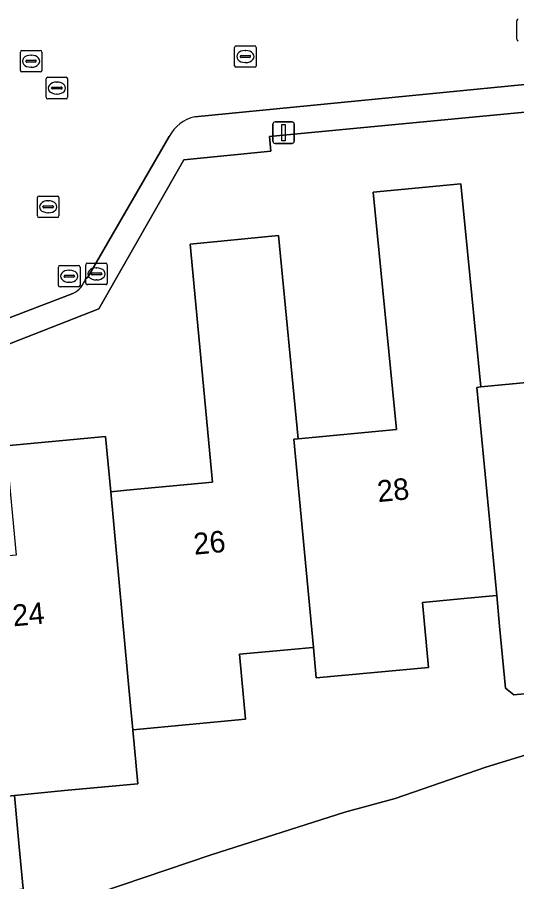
# Model space of a CAD drawing. Extents: x 157793 to 159380, y 380877 to 382313.
# Drawn here: x 158433.42 to 158456.61, y 381160.97 to 381201.1 of the extents above; entities that cross this region are included whole.
import ezdxf

# ---------------------------------------------------------------- set-up
doc = ezdxf.new("R2010")
doc.units = 0
for name, color, linetype in [('IMGEO_Brandkraan', 7, 'Continuous'), ('IMGEO_Erf', 7, 'Continuous'), ('IMGEO_Kolk', 7, 'Continuous'), ('IMGEO_Lichtmast', 7, 'Continuous'), ('IMGEO_Oever', 7, 'Continuous'), ('IMGEO_Pand', 7, 'Continuous'), ('IMGEO_Pand_nummerreeks', 7, 'Continuous'), ('IMGEO_Rijbaan_lokaal_open', 7, 'Continuous'), ('IMGEO_Rioolput', 7, 'Continuous'), ('IMGEO_Voetpad_open', 7, 'Continuous')]:
    doc.layers.add(name, color=color, linetype=linetype)

msp = doc.modelspace()

# ---------------------------------------------------------------- linework, layer by layer
at = {"layer": 'IMGEO_Brandkraan'}
for p, q in [((158436.596, 381188.76), (158436.596, 381189.612)), ((158436.671, 381189.686), (158437.523, 381189.686)), ((158437.084, 381189.466), (158437.109, 381189.466)), ((158437.597, 381189.612), (158437.597, 381188.76)), ((158436.855, 381189.18), (158436.855, 381189.192)), ((158437.293, 381189.143), (158436.895, 381189.143)), ((158436.898, 381189.229), (158437.296, 381189.229)), ((158437.339, 381189.192), (158437.339, 381189.18)), ((158437.523, 381188.686), (158436.671, 381188.686)), ((158437.107, 381188.906), (158437.082, 381188.906))]:
    msp.add_line(p, q, dxfattribs=at)
for points in [[(158436.596, 381188.76), (158436.596, 381189.612)], [(158436.671, 381189.686), (158437.523, 381189.686)], [(158437.597, 381189.612), (158437.597, 381188.76)], [(158437.523, 381188.686), (158436.671, 381188.686)]]:
    msp.add_lwpolyline(points, dxfattribs=at)
for centre, radius, start, end in [((158436.673, 381189.61), 0.0765, 91.552, 178.448), ((158436.673, 381189.61), 0.0765, 91.552, 178.448), ((158437.521, 381189.61), 0.0765, 1.552, 88.448), ((158437.521, 381189.61), 0.0765, 1.552, 88.448), ((158436.895, 381189.189), 0.0403, 85.8775, 175.7526), ((158436.892, 381189.179), 0.0366, 178.938, 274.7102), ((158437.296, 381189.186), 0.043, 264.8664, 352.4533), ((158437.3, 381189.191), 0.0386, 1.7309, 96.639), ((158436.673, 381188.762), 0.0765, 181.552, 268.448), ((158436.673, 381188.762), 0.0765, 181.552, 268.448), ((158437.521, 381188.762), 0.0765, 271.552, 358.448), ((158437.521, 381188.762), 0.0765, 271.552, 358.448)]:
    msp.add_arc(centre, radius, start, end, dxfattribs=at)
for centre, major_axis, ratio, start_param, end_param in [((158437.083, 381189.186), (-0.387, 0.002), 0.722429, 4.712389, 7.853982), ((158437.108, 381189.186), (-0.39, 0.002), 0.717154, 1.570796, 4.712389)]:
    msp.add_ellipse(centre, major_axis=major_axis, ratio=ratio, start_param=start_param, end_param=end_param, dxfattribs=at)
at = {"layer": 'IMGEO_Erf'}
for points in [[(158437.246, 381160.472), (158442.422, 381162.212), (158448.623, 381164.199), (158450.965, 381164.837), (158455.184, 381166.285), (158458.213, 381167.208), (158462.978, 381168.229), (158465.934, 381168.665), (158482.116, 381170.34), (158494.752, 381172.28), (158498.036, 381172.994), (158500.751, 381174.141), (158502.381, 381175.376), (158503.675, 381176.792), (158504.257, 381177.69), (158505.004, 381179.524), (158505.458, 381182.578), (158505.469, 381183.437), (158505.318, 381184.258), (158502.748, 381197.597), (158500.66, 381208.431)], [(158461.541, 381197.122), (158445.123, 381195.558), (158445.198, 381194.878), (158441.151, 381194.476), (158437.204, 381187.562), (158373.758, 381162.728)], [(158432.885, 381181.204), (158437.52, 381181.642), (158437.758, 381179.072), (158437.908, 381179.086), (158438.652, 381179.156), (158442.489, 381179.518), (158441.448, 381190.573), (158445.554, 381190.963), (158446.459, 381181.527), (158451.028, 381181.964), (158449.942, 381192.982), (158454.02, 381193.369), (158454.952, 381183.935), (158459.521, 381184.373)], [(158458.234, 381169.806), (158456.474, 381169.644), (158456.095, 381169.946), (158455.818, 381172.838), (158455.683, 381174.25), (158455.502, 381174.233), (158454.332, 381174.125), (158452.241, 381173.932), (158452.518, 381170.919), (158447.299, 381170.439), (158447.167, 381171.841), (158446.978, 381171.823), (158446.307, 381171.761), (158443.737, 381171.524), (158444.013, 381168.511), (158438.781, 381168.026), (158439.013, 381165.519), (158435.617, 381165.195), (158433.289, 381164.973), (158433.505, 381162.593), (158433.683, 381160.63)]]:
    msp.add_lwpolyline(points, dxfattribs=at)
at = {"layer": 'IMGEO_Kolk'}
for p, q in [((158456.611, 381200.081), (158456.611, 381200.933)), ((158443.512, 381198.852), (158443.512, 381199.704)), ((158443.587, 381199.778), (158444.439, 381199.778)), ((158444, 381199.558), (158444.025, 381199.558)), ((158444.513, 381199.704), (158444.513, 381198.852)), ((158443.771, 381199.272), (158443.771, 381199.284)), ((158444.209, 381199.235), (158443.811, 381199.235)), ((158443.814, 381199.321), (158444.212, 381199.321)), ((158444.255, 381199.284), (158444.255, 381199.272)), ((158444.439, 381198.778), (158443.587, 381198.778)), ((158444.023, 381198.998), (158443.998, 381198.998))]:
    msp.add_line(p, q, dxfattribs=at)
for points in [[(158456.611, 381200.081), (158456.611, 381200.933)], [(158443.512, 381198.852), (158443.512, 381199.704)], [(158443.587, 381199.778), (158444.439, 381199.778)], [(158444.513, 381199.704), (158444.513, 381198.852)], [(158444.439, 381198.778), (158443.587, 381198.778)]]:
    msp.add_lwpolyline(points, dxfattribs=at)
for centre, radius, start, end in [((158456.688, 381200.931), 0.0765, 91.552, 178.448), ((158456.688, 381200.931), 0.0765, 91.552, 178.448), ((158456.688, 381200.083), 0.0765, 181.552, 268.448), ((158456.688, 381200.083), 0.0765, 181.552, 268.448), ((158443.589, 381199.702), 0.0765, 91.552, 178.448), ((158443.589, 381199.702), 0.0765, 91.552, 178.448), ((158444.437, 381199.702), 0.0765, 1.552, 88.448), ((158444.437, 381199.702), 0.0765, 1.552, 88.448), ((158443.811, 381199.281), 0.0403, 85.8775, 175.7526), ((158443.808, 381199.271), 0.0366, 178.938, 274.7102), ((158444.212, 381199.278), 0.043, 264.8664, 352.4533), ((158444.216, 381199.283), 0.0386, 1.7309, 96.639), ((158443.589, 381198.854), 0.0765, 181.552, 268.448), ((158443.589, 381198.854), 0.0765, 181.552, 268.448), ((158444.437, 381198.854), 0.0765, 271.552, 358.448), ((158444.437, 381198.854), 0.0765, 271.552, 358.448)]:
    msp.add_arc(centre, radius, start, end, dxfattribs=at)
for centre, major_axis, ratio, start_param, end_param in [((158443.999, 381199.278), (-0.387, 0.002), 0.722429, 4.712389, 7.853982), ((158444.024, 381199.278), (-0.39, 0.002), 0.717154, 1.570796, 4.712389)]:
    msp.add_ellipse(centre, major_axis=major_axis, ratio=ratio, start_param=start_param, end_param=end_param, dxfattribs=at)
at = {"layer": 'IMGEO_Lichtmast'}
for p, q in [((158445.388, 381196.245), (158446.178, 381196.245)), ((158446.178, 381196.245), (158445.388, 381196.245)), ((158445.288, 381195.345), (158445.288, 381196.145)), ((158445.288, 381196.145), (158445.288, 381195.345)), ((158446.278, 381196.145), (158446.278, 381195.345)), ((158446.278, 381195.345), (158446.278, 381196.145)), ((158446.178, 381195.245), (158445.388, 381195.245)), ((158445.388, 381195.245), (158446.178, 381195.245))]:
    msp.add_line(p, q, dxfattribs=at)
msp.add_lwpolyline([(158445.708, 381196.12), (158445.858, 381196.12), (158445.858, 381195.37), (158445.708, 381195.37), (158445.708, 381196.12)], dxfattribs=at)
for centre, start, end in [((158445.388, 381196.145), 90, 180), ((158445.388, 381196.145), 90, 180), ((158446.178, 381196.145), 0, 90), ((158446.178, 381196.145), 360, 90), ((158445.388, 381195.345), 180, 270), ((158445.388, 381195.345), 180, 270), ((158446.178, 381195.345), 270, 0), ((158446.178, 381195.345), 270, 0)]:
    msp.add_arc(centre, 0.1, start, end, dxfattribs=at)
at = {"layer": 'IMGEO_Oever'}
msp.add_lwpolyline([(158500.66, 381208.431), (158502.748, 381197.597), (158505.318, 381184.258), (158505.469, 381183.437), (158505.458, 381182.578), (158505.004, 381179.524), (158504.257, 381177.69), (158503.675, 381176.792), (158502.381, 381175.376), (158500.751, 381174.141), (158498.036, 381172.994), (158494.752, 381172.28), (158482.116, 381170.34), (158465.934, 381168.665), (158462.978, 381168.229), (158458.213, 381167.208), (158455.184, 381166.285), (158450.965, 381164.837), (158448.623, 381164.199), (158442.422, 381162.212), (158437.246, 381160.472)], dxfattribs=at)
at = {"layer": 'IMGEO_Pand'}
for points in [[(158463.458, 381186.315), (158462.539, 381195.771), (158458.457, 381195.374), (158459.521, 381184.373), (158454.952, 381183.935), (158454.759, 381183.916), (158455.683, 381174.25), (158455.818, 381172.838), (158456.095, 381169.946), (158456.474, 381169.644), (158458.234, 381169.806), (158458.697, 381170.42), (158458.442, 381173.08), (158461.031, 381173.318), (158463.02, 381173.501), (158462.736, 381176.514), (158464.184, 381176.648), (158464.084, 381177.703), (158463.273, 381186.297)], [(158454.952, 381183.935), (158454.02, 381193.369), (158449.942, 381192.982), (158451.028, 381181.964), (158446.459, 381181.527), (158446.259, 381181.508), (158447.167, 381171.841), (158447.299, 381170.439), (158452.518, 381170.919), (158452.241, 381173.932), (158454.332, 381174.125), (158455.502, 381174.233), (158455.683, 381174.25), (158454.759, 381183.916)], [(158446.459, 381181.527), (158445.554, 381190.963), (158441.448, 381190.573), (158442.489, 381179.518), (158438.652, 381179.156), (158437.908, 381179.086), (158437.758, 381179.072), (158438.678, 381169.136), (158438.737, 381168.506), (158438.781, 381168.026), (158444.013, 381168.511), (158443.737, 381171.524), (158446.307, 381171.761), (158446.978, 381171.823), (158447.167, 381171.841), (158446.259, 381181.508)], [(158437.758, 381179.072), (158437.52, 381181.642), (158432.885, 381181.204), (158432.913, 381180.903), (158433.363, 381176.124), (158430.247, 381175.831), (158429.519, 381175.762), (158429.351, 381175.746), (158430.38, 381164.696), (158433.289, 381164.973), (158435.617, 381165.195), (158439.013, 381165.519), (158438.781, 381168.026), (158438.737, 381168.506), (158438.678, 381169.136)], [(158433.505, 381162.593), (158433.289, 381164.973), (158430.38, 381164.696), (158430.599, 381162.16), (158430.642, 381161.661), (158430.756, 381160.351), (158433.683, 381160.63)]]:
    msp.add_lwpolyline(points, close=True, dxfattribs=at)
at = {"layer": 'IMGEO_Rijbaan_lokaal_open'}
for points in [[(158436.443, 381203.658), (158431.533, 381203.205), (158432.528, 381192.337), (158426.639, 381190.054), (158428.505, 381185.406), (158435.998, 381188.28)], [(158441.66, 381196.48), (158457.774, 381198.055), (158457.257, 381203.058)], [(158436.586, 381188.964), (158436.693, 381189.037), (158440.473, 381195.569)]]:
    msp.add_lwpolyline(points, dxfattribs=at)
for centre, radius, start, end in [((158442.055, 381194.737), 1.787, 102.762, 152.2491), ((158435.529, 381189.278), 1.103, 295.1791, 343.4529)]:
    msp.add_arc(centre, radius, start, end, dxfattribs=at)
at = {"layer": 'IMGEO_Rioolput'}
for p, q in [((158433.559, 381198.635), (158433.559, 381199.487)), ((158433.634, 381199.561), (158434.486, 381199.561)), ((158434.56, 381199.487), (158434.56, 381198.635)), ((158433.818, 381199.055), (158433.818, 381199.067)), ((158433.861, 381199.104), (158434.259, 381199.104)), ((158434.047, 381199.341), (158434.072, 381199.341)), ((158434.302, 381199.067), (158434.302, 381199.055)), ((158434.256, 381199.018), (158433.858, 381199.018)), ((158434.07, 381198.781), (158434.045, 381198.781)), ((158434.486, 381198.561), (158433.634, 381198.561)), ((158434.754, 381197.387), (158434.754, 381198.239)), ((158434.829, 381198.313), (158435.681, 381198.313)), ((158435.755, 381198.239), (158435.755, 381197.387)), ((158435.013, 381197.807), (158435.013, 381197.819)), ((158435.056, 381197.856), (158435.454, 381197.856)), ((158435.242, 381198.093), (158435.267, 381198.093)), ((158435.497, 381197.819), (158435.497, 381197.807)), ((158435.451, 381197.77), (158435.053, 381197.77)), ((158435.265, 381197.533), (158435.24, 381197.533)), ((158435.681, 381197.313), (158434.829, 381197.313)), ((158434.351, 381191.875), (158434.351, 381192.727)), ((158434.426, 381192.801), (158435.278, 381192.801)), ((158435.352, 381192.727), (158435.352, 381191.875)), ((158434.61, 381192.295), (158434.61, 381192.307)), ((158435.048, 381192.258), (158434.65, 381192.258)), ((158434.653, 381192.344), (158435.051, 381192.344)), ((158434.839, 381192.581), (158434.864, 381192.581)), ((158435.094, 381192.307), (158435.094, 381192.295)), ((158435.278, 381191.801), (158434.426, 381191.801)), ((158434.862, 381192.021), (158434.837, 381192.021)), ((158435.33, 381188.652), (158435.33, 381189.504)), ((158435.405, 381189.578), (158436.257, 381189.578)), ((158436.331, 381189.504), (158436.331, 381188.652)), ((158435.589, 381189.072), (158435.589, 381189.084)), ((158436.027, 381189.035), (158435.629, 381189.035)), ((158435.632, 381189.121), (158436.03, 381189.121)), ((158435.818, 381189.358), (158435.843, 381189.358)), ((158436.073, 381189.084), (158436.073, 381189.072)), ((158435.841, 381188.798), (158435.816, 381188.798)), ((158436.257, 381188.578), (158435.405, 381188.578))]:
    msp.add_line(p, q, dxfattribs=at)
for points in [[(158433.559, 381198.635), (158433.559, 381199.487)], [(158433.634, 381199.561), (158434.486, 381199.561)], [(158434.56, 381199.487), (158434.56, 381198.635)], [(158434.486, 381198.561), (158433.634, 381198.561)], [(158434.754, 381197.387), (158434.754, 381198.239)], [(158434.829, 381198.313), (158435.681, 381198.313)], [(158435.755, 381198.239), (158435.755, 381197.387)], [(158435.681, 381197.313), (158434.829, 381197.313)], [(158434.351, 381191.875), (158434.351, 381192.727)], [(158434.426, 381192.801), (158435.278, 381192.801)], [(158435.352, 381192.727), (158435.352, 381191.875)], [(158435.278, 381191.801), (158434.426, 381191.801)], [(158435.33, 381188.652), (158435.33, 381189.504)], [(158435.405, 381189.578), (158436.257, 381189.578)], [(158436.331, 381189.504), (158436.331, 381188.652)], [(158436.257, 381188.578), (158435.405, 381188.578)]]:
    msp.add_lwpolyline(points, dxfattribs=at)
for centre, radius, start, end in [((158433.636, 381199.485), 0.0765, 91.552, 178.448), ((158433.636, 381199.485), 0.0765, 91.552, 178.448), ((158434.484, 381199.485), 0.0765, 1.552, 88.448), ((158434.484, 381199.485), 0.0765, 1.552, 88.448), ((158433.858, 381199.064), 0.0403, 85.8775, 175.7526), ((158433.855, 381199.054), 0.0366, 178.938, 274.7102), ((158434.259, 381199.061), 0.043, 264.8664, 352.4533), ((158434.263, 381199.066), 0.0386, 1.7309, 96.639), ((158433.636, 381198.637), 0.0765, 181.552, 268.448), ((158433.636, 381198.637), 0.0765, 181.552, 268.448), ((158434.484, 381198.637), 0.0765, 271.552, 358.448), ((158434.484, 381198.637), 0.0765, 271.552, 358.448), ((158434.831, 381198.237), 0.0765, 91.552, 178.448), ((158434.831, 381198.237), 0.0765, 91.552, 178.448), ((158435.679, 381198.237), 0.0765, 1.552, 88.448), ((158435.679, 381198.237), 0.0765, 1.552, 88.448), ((158435.053, 381197.816), 0.0403, 85.8775, 175.7526), ((158435.458, 381197.818), 0.0386, 1.7309, 96.639), ((158435.05, 381197.806), 0.0366, 178.938, 274.7102), ((158435.454, 381197.813), 0.043, 264.8664, 352.4533), ((158434.831, 381197.389), 0.0765, 181.552, 268.448), ((158434.831, 381197.389), 0.0765, 181.552, 268.448), ((158435.679, 381197.389), 0.0765, 271.552, 358.448), ((158435.679, 381197.389), 0.0765, 271.552, 358.448), ((158434.428, 381192.725), 0.0765, 91.552, 178.448), ((158434.428, 381192.725), 0.0765, 91.552, 178.448), ((158435.276, 381192.725), 0.0765, 1.552, 88.448), ((158435.276, 381192.725), 0.0765, 1.552, 88.448), ((158434.65, 381192.304), 0.0403, 85.8775, 175.7526), ((158434.647, 381192.294), 0.0366, 178.938, 274.7102), ((158435.051, 381192.301), 0.043, 264.8664, 352.4533), ((158435.055, 381192.306), 0.0386, 1.7309, 96.639), ((158434.428, 381191.877), 0.0765, 181.552, 268.448), ((158434.428, 381191.877), 0.0765, 181.552, 268.448), ((158435.276, 381191.877), 0.0765, 271.552, 358.448), ((158435.276, 381191.877), 0.0765, 271.552, 358.448), ((158435.407, 381189.502), 0.0765, 91.552, 178.448), ((158435.407, 381189.502), 0.0765, 91.552, 178.448), ((158436.255, 381189.502), 0.0765, 1.552, 88.448), ((158436.255, 381189.502), 0.0765, 1.552, 88.448), ((158435.629, 381189.081), 0.0403, 85.8775, 175.7526), ((158435.626, 381189.071), 0.0366, 178.938, 274.7102), ((158436.03, 381189.078), 0.043, 264.8664, 352.4533), ((158436.034, 381189.083), 0.0386, 1.7309, 96.639), ((158435.407, 381188.654), 0.0765, 181.552, 268.448), ((158435.407, 381188.654), 0.0765, 181.552, 268.448), ((158436.255, 381188.654), 0.0765, 271.552, 358.448), ((158436.255, 381188.654), 0.0765, 271.552, 358.448)]:
    msp.add_arc(centre, radius, start, end, dxfattribs=at)
for centre, major_axis, ratio, start_param, end_param in [((158434.046, 381199.061), (-0.387, 0.002), 0.722429, 4.712389, 7.853982), ((158434.071, 381199.061), (-0.39, 0.002), 0.717154, 1.570796, 4.712389), ((158435.241, 381197.813), (-0.387, 0.002), 0.722429, 4.712389, 7.853982), ((158435.266, 381197.813), (-0.39, 0.002), 0.717154, 1.570796, 4.712389), ((158434.838, 381192.301), (-0.387, 0.002), 0.722429, 4.712389, 7.853982), ((158434.863, 381192.301), (-0.39, 0.002), 0.717154, 1.570796, 4.712389), ((158435.817, 381189.078), (-0.387, 0.002), 0.722429, 4.712389, 7.853982), ((158435.842, 381189.078), (-0.39, 0.002), 0.717154, 1.570796, 4.712389)]:
    msp.add_ellipse(centre, major_axis=major_axis, ratio=ratio, start_param=start_param, end_param=end_param, dxfattribs=at)
at = {"layer": 'IMGEO_Voetpad_open'}
for points in [[(158471.433, 381199.347), (158461.221, 381198.372), (158457.774, 381198.055), (158441.66, 381196.48)], [(158435.998, 381188.28), (158428.505, 381185.406), (158425.292, 381184.147), (158382.725, 381167.434), (158380.022, 381166.386), (158374.1, 381164.032), (158345.684, 381144.763), (158345.336, 381148.653), (158349.465, 381151.46), (158344.919, 381151.126), (158343.198, 381150.791), (158343.94, 381142.482), (158373.758, 381162.728), (158437.204, 381187.562), (158441.151, 381194.476), (158445.198, 381194.878), (158445.123, 381195.558), (158461.541, 381197.122), (158467.081, 381197.838), (158471.171, 381198.233), (158472.258, 381198.299), (158472.526, 381194.816), (158473.576, 381194.917), (158473.341, 381197.829)], [(158440.473, 381195.569), (158436.693, 381189.037), (158436.586, 381188.964)]]:
    msp.add_lwpolyline(points, dxfattribs=at)
for centre, radius, start, end in [((158442.055, 381194.737), 1.787, 102.762, 152.2491), ((158435.529, 381189.278), 1.103, 295.1791, 343.4529)]:
    msp.add_arc(centre, radius, start, end, dxfattribs=at)

# ---------------------------------------------------------------- texts
at = {"layer": 'IMGEO_Pand_nummerreeks'}
for s, rotation, p in [('28', 5.466, (158450.177, 381178.587)), ('26', 5.3858, (158441.645, 381176.145)), ('24', 5.3801, (158433.24, 381172.818))]:
    msp.add_text(s, height=1, rotation=rotation, dxfattribs=at).set_placement(p)

doc.saveas('drawing.dxf')
